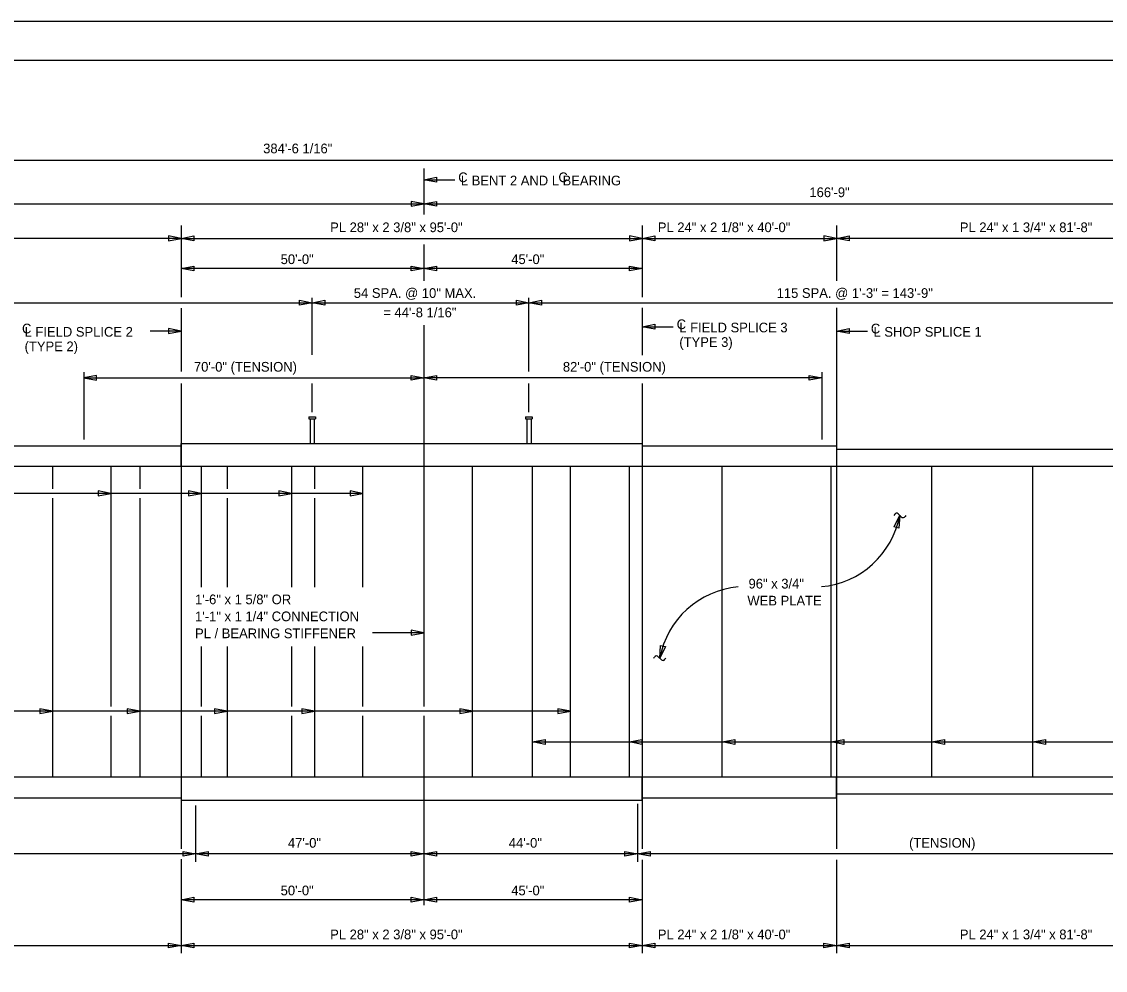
# Model space of a CAD drawing. Extents: x -305 to -161, y -187 to -99.
# Drawn here: x -249.7 to -193.9, y -148.4 to -99.5 of the extents above; entities that cross this region are included whole.
import ezdxf

# ---------------------------------------------------------------- set-up
doc = ezdxf.new("R2010")
doc.units = 0
for name, color, linetype in [('BR_AUTO DIMENSION', 7, 'Continuous'), ('BR_BORDER LINES', 7, 'Continuous'), ('BR_CENTER LINES', 7, 'Continuous'), ('BR_STRUCTURAL STEEL', 7, 'Continuous'), ('BR_TEXT', 7, 'Continuous'), ('Default', 7, 'Continuous'), ('Level 31', 7, 'Continuous')]:
    doc.layers.add(name, color=color, linetype=linetype)

msp = doc.modelspace()

# ---------------------------------------------------------------- linework, layer by layer
at = {"layer": 'BR_AUTO DIMENSION'}
for p, q in [((-284.433, -106.618), (-186.619, -106.618)), ((-228.973, -107.634), (-227.375, -107.634)), ((-284.433, -108.876), (-228.974, -108.876)), ((-228.974, -108.876), (-186.619, -108.876)), ((-241.473, -110.653), (-268.973, -110.653)), ((-241.473, -110.653), (-217.723, -110.653)), ((-217.723, -110.653), (-207.723, -110.653)), ((-186.619, -110.653), (-207.723, -110.653)), ((-228.973, -112.204), (-241.473, -112.204)), ((-217.723, -112.204), (-228.973, -112.204)), ((-234.724, -116.66), (-234.724, -113.721)), ((-223.557, -117.52), (-223.557, -113.721)), ((-282.099, -113.971), (-232.058, -113.971)), ((-282.099, -113.971), (-234.724, -113.971)), ((-234.724, -113.971), (-223.557, -113.971)), ((-223.557, -113.971), (-187.869, -113.971)), ((-241.473, -115.428), (-243.072, -115.428)), ((-217.723, -115.207), (-216.125, -115.207)), ((-207.723, -115.428), (-206.125, -115.428)), ((-246.473, -117.55), (-246.473, -121.025)), ((-208.473, -117.55), (-208.473, -121.025)), ((-246.473, -117.84), (-228.973, -117.84)), ((-234.724, -119.6), (-234.724, -118.13)), ((-208.473, -117.84), (-228.973, -117.84)), ((-223.557, -119.6), (-223.557, -118.13)), ((-232.123, -123.792), (-287.791, -123.792)), ((-228.973, -130.97), (-231.622, -130.97)), ((-221.422, -135.013), (-287.791, -135.013)), ((-223.369, -136.601), (-183.069, -136.601)), ((-240.723, -139.874), (-240.723, -142.773)), ((-217.973, -139.78), (-217.973, -142.773)), ((-240.723, -142.367), (-284.433, -142.367)), ((-228.973, -142.367), (-240.723, -142.367)), ((-217.973, -142.367), (-228.973, -142.367)), ((-186.619, -142.367), (-217.973, -142.367)), ((-228.973, -144.726), (-241.473, -144.726)), ((-217.723, -144.726), (-228.973, -144.726)), ((-268.973, -147.085), (-241.473, -147.085)), ((-241.473, -147.085), (-217.723, -147.085)), ((-217.723, -147.085), (-207.723, -147.085)), ((-207.723, -147.085), (-186.619, -147.085))]:
    msp.add_line(p, q, dxfattribs=at)
for points in [[(-228.323, -107.759), (-228.973, -107.634), (-228.323, -107.509)], [(-229.623, -109.001), (-228.973, -108.876), (-229.623, -108.751)], [(-228.323, -109.001), (-228.973, -108.876), (-228.323, -108.751)], [(-242.123, -110.778), (-241.473, -110.653), (-242.123, -110.528)], [(-240.823, -110.778), (-241.473, -110.653), (-240.823, -110.528)], [(-218.373, -110.778), (-217.723, -110.653), (-218.373, -110.528)], [(-217.073, -110.778), (-217.723, -110.653), (-217.073, -110.528)], [(-208.373, -110.778), (-207.723, -110.653), (-208.373, -110.528)], [(-207.073, -110.778), (-207.723, -110.653), (-207.073, -110.528)], [(-240.823, -112.329), (-241.473, -112.204), (-240.823, -112.079)], [(-229.623, -112.079), (-228.973, -112.204), (-229.623, -112.329)], [(-228.323, -112.329), (-228.973, -112.204), (-228.323, -112.079)], [(-218.373, -112.079), (-217.723, -112.204), (-218.373, -112.329)], [(-235.374, -113.846), (-234.724, -113.971), (-235.374, -114.096)], [(-234.074, -114.096), (-234.724, -113.971), (-234.074, -113.846)], [(-224.207, -113.846), (-223.557, -113.971), (-224.207, -114.096)], [(-222.907, -114.096), (-223.557, -113.971), (-222.907, -113.846)], [(-242.123, -115.553), (-241.473, -115.428), (-242.123, -115.303)], [(-217.073, -115.332), (-217.723, -115.207), (-217.073, -115.082)], [(-207.073, -115.553), (-207.723, -115.428), (-207.073, -115.303)], [(-245.823, -117.715), (-246.473, -117.84), (-245.823, -117.965)], [(-229.623, -117.715), (-228.973, -117.84), (-229.623, -117.965)], [(-228.323, -117.965), (-228.973, -117.84), (-228.323, -117.715)], [(-209.123, -117.715), (-208.473, -117.84), (-209.123, -117.965)], [(-245.735, -123.917), (-245.085, -123.792), (-245.735, -123.667)], [(-241.089, -123.917), (-240.439, -123.792), (-241.089, -123.667)], [(-236.442, -123.917), (-235.792, -123.792), (-236.442, -123.667)], [(-232.773, -123.917), (-232.123, -123.792), (-232.773, -123.667)], [(-204.748, -125.52), (-204.465, -124.922), (-204.506, -125.582)], [(-229.623, -131.095), (-228.973, -130.97), (-229.623, -130.845)], [(-216.534, -131.689), (-216.817, -132.287), (-216.776, -131.627)], [(-248.749, -135.138), (-248.099, -135.013), (-248.749, -134.888)], [(-244.249, -135.138), (-243.599, -135.013), (-244.249, -134.888)], [(-239.749, -135.138), (-239.099, -135.013), (-239.749, -134.888)], [(-235.249, -135.138), (-234.599, -135.013), (-235.249, -134.888)], [(-227.123, -135.138), (-226.473, -135.013), (-227.123, -134.888)], [(-222.072, -135.138), (-221.422, -135.013), (-222.072, -134.888)], [(-222.719, -136.726), (-223.369, -136.601), (-222.719, -136.476)], [(-217.739, -136.726), (-218.389, -136.601), (-217.739, -136.476)], [(-212.952, -136.726), (-213.602, -136.601), (-212.952, -136.476)], [(-207.351, -136.726), (-208.001, -136.601), (-207.351, -136.476)], [(-202.156, -136.726), (-202.806, -136.601), (-202.156, -136.476)], [(-196.962, -136.726), (-197.612, -136.601), (-196.962, -136.476)], [(-241.373, -142.242), (-240.723, -142.367), (-241.373, -142.492)], [(-240.073, -142.492), (-240.723, -142.367), (-240.073, -142.242)], [(-229.623, -142.242), (-228.973, -142.367), (-229.623, -142.492)], [(-228.323, -142.492), (-228.973, -142.367), (-228.323, -142.242)], [(-218.623, -142.242), (-217.973, -142.367), (-218.623, -142.492)], [(-217.323, -142.492), (-217.973, -142.367), (-217.323, -142.242)], [(-240.823, -144.851), (-241.473, -144.726), (-240.823, -144.601)], [(-229.623, -144.601), (-228.973, -144.726), (-229.623, -144.851)], [(-228.323, -144.851), (-228.973, -144.726), (-228.323, -144.601)], [(-218.373, -144.601), (-217.723, -144.726), (-218.373, -144.851)], [(-242.123, -146.96), (-241.473, -147.085), (-242.123, -147.21)], [(-240.823, -147.21), (-241.473, -147.085), (-240.823, -146.96)], [(-218.373, -146.96), (-217.723, -147.085), (-218.373, -147.21)], [(-217.073, -147.21), (-217.723, -147.085), (-217.073, -146.96)], [(-208.373, -146.96), (-207.723, -147.085), (-208.373, -147.21)], [(-207.073, -147.21), (-207.723, -147.085), (-207.073, -146.96)]]:
    msp.add_lwpolyline(points, close=True, dxfattribs=at)
for centre, start, end in [((-208.89, -124.118), 274.9624, 349.7037), ((-212.392, -133.091), 94.9624, 169.7037)]:
    msp.add_arc(centre, 4.497, start, end, dxfattribs=at)
at = {"layer": 'BR_BORDER LINES'}
msp.add_line((-163.178, -101.489), (-297.843, -101.489), dxfattribs=at)
at = {"layer": 'BR_CENTER LINES'}
for p, q in [((-228.973, -107.059), (-228.973, -109.43)), ((-241.473, -109.997), (-241.473, -113.69)), ((-217.723, -109.997), (-217.723, -113.69)), ((-207.723, -109.997), (-207.723, -112.835)), ((-228.973, -110.967), (-228.973, -112.835)), ((-241.473, -114.253), (-241.473, -117.52)), ((-217.723, -114.23), (-217.723, -116.675)), ((-207.723, -114.23), (-207.723, -142.108)), ((-228.973, -115.133), (-228.973, -122.412)), ((-241.473, -118.13), (-241.473, -124.614)), ((-217.723, -118.13), (-217.723, -142.11)), ((-241.473, -124.614), (-241.473, -142.109)), ((-228.973, -138.412), (-228.973, -145.014)), ((-241.473, -142.631), (-241.473, -147.486)), ((-217.723, -142.664), (-217.723, -147.486)), ((-207.723, -142.667), (-207.723, -147.486))]:
    msp.add_line(p, q, dxfattribs=at)
at = {"layer": 'BR_STRUCTURAL STEEL'}
for p, q in [((-268.973, -121.35), (-241.473, -121.35)), ((-241.473, -122.412), (-241.473, -121.225)), ((-241.473, -121.225), (-217.723, -121.225)), ((-217.723, -121.225), (-217.723, -122.412)), ((-217.723, -121.35), (-207.723, -121.35)), ((-207.723, -121.35), (-207.723, -122.412)), ((-186.619, -121.537), (-207.723, -121.537)), ((-186.619, -122.412), (-284.433, -122.412)), ((-248.099, -122.412), (-248.099, -123.55)), ((-245.085, -122.412), (-245.085, -134.771)), ((-243.599, -122.412), (-243.599, -123.55)), ((-240.439, -122.412), (-240.439, -128.632)), ((-239.099, -122.412), (-239.099, -123.55)), ((-235.792, -122.412), (-235.792, -128.632)), ((-234.599, -122.412), (-234.599, -123.55)), ((-232.123, -122.412), (-232.123, -128.632)), ((-228.973, -122.412), (-228.973, -134.771)), ((-226.473, -138.412), (-226.473, -122.412)), ((-223.369, -138.412), (-223.369, -122.412)), ((-221.422, -138.412), (-221.422, -122.412)), ((-218.389, -138.412), (-218.389, -122.412)), ((-213.602, -138.412), (-213.602, -122.412)), ((-208.001, -138.412), (-208.001, -122.412)), ((-202.806, -138.412), (-202.806, -122.412)), ((-197.612, -138.412), (-197.612, -122.412)), ((-248.099, -124.034), (-248.099, -138.412)), ((-243.599, -124.034), (-243.599, -138.412)), ((-239.099, -124.034), (-239.099, -128.632)), ((-234.599, -124.034), (-234.599, -128.632)), ((-240.439, -131.688), (-240.439, -134.771)), ((-239.099, -131.688), (-239.099, -138.412)), ((-235.792, -131.688), (-235.792, -134.771)), ((-234.599, -131.688), (-234.599, -138.412)), ((-232.123, -131.688), (-232.123, -134.771)), ((-245.085, -135.255), (-245.085, -138.412)), ((-240.439, -135.255), (-240.439, -138.412)), ((-235.792, -135.255), (-235.792, -138.412)), ((-232.123, -135.255), (-232.123, -138.412)), ((-228.973, -135.255), (-228.973, -138.412)), ((-186.619, -138.412), (-284.433, -138.412)), ((-241.473, -138.412), (-241.473, -139.6)), ((-217.723, -139.6), (-217.723, -138.412)), ((-207.723, -139.475), (-207.723, -138.412)), ((-268.973, -139.475), (-241.473, -139.475)), ((-217.724, -139.475), (-207.723, -139.475)), ((-186.619, -139.287), (-207.723, -139.287)), ((-241.473, -139.6), (-217.724, -139.6))]:
    msp.add_line(p, q, dxfattribs=at)
at = {"layer": 'BR_TEXT'}
for p, q in [((-204.725, -124.869), (-204.768, -124.93)), ((-204.384, -124.996), (-204.547, -124.847)), ((-204.15, -124.93), (-204.18, -124.976)), ((-217.131, -132.279), (-217.102, -132.233)), ((-216.898, -132.213), (-216.735, -132.362)), ((-216.557, -132.34), (-216.514, -132.279))]:
    msp.add_line(p, q, dxfattribs=at)
for centre, radius, start, end in [((-204.627, -124.922), 0.111, 43.4519, 151.7375), ((-204.29, -124.915), 0.125, 221.007, 330.8059), ((-216.992, -132.294), 0.125, 41.007, 150.8059), ((-216.654, -132.287), 0.111, 223.4519, 331.7375)]:
    msp.add_arc(centre, radius, start, end, dxfattribs=at)
at = {"layer": 'Default'}
for p, q in [((-234.896, -119.85), (-234.896, -119.944)), ((-234.896, -119.85), (-234.552, -119.85)), ((-234.896, -119.944), (-234.552, -119.944)), ((-234.834, -119.944), (-234.834, -121.225)), ((-234.615, -119.944), (-234.615, -121.225)), ((-234.552, -119.85), (-234.552, -119.944)), ((-223.729, -119.85), (-223.729, -119.944)), ((-223.729, -119.85), (-223.385, -119.85)), ((-223.729, -119.944), (-223.385, -119.944)), ((-223.666, -119.944), (-223.666, -121.225)), ((-223.447, -119.944), (-223.447, -121.225)), ((-223.385, -119.85), (-223.385, -119.944))]:
    msp.add_line(p, q, dxfattribs=at)
at = {"layer": 'Level 31'}
msp.add_lwpolyline([(-305.176, -187.489), (-161.176, -187.489), (-161.176, -99.489), (-305.176, -99.489)], close=True, dxfattribs=at)

# ---------------------------------------------------------------- texts
at = {"layer": 'BR_AUTO DIMENSION'}
for s, p in [('384\'-6 1/16"', (-237.246, -106.272)), ('166\'-9"', (-209.116, -108.53)), ('PL 28" x 2 3/8" x 95\'-0"', (-233.797, -110.334)), ('PL 24" x 2 1/8" x 40\'-0"', (-216.922, -110.334)), ('PL 24" x 1 3/4" x 81\'-8"', (-201.37, -110.334)), ('50\'-0"', (-236.345, -111.979)), ('45\'-0"', (-224.47, -111.979)), (' 82\'-0" (TENSION)', (-221.997, -117.521)), ('96" x 3/4" ', (-212.251, -128.694)), ('WEB PLATE', (-212.309, -129.569)), ('47\'-0"', (-235.97, -142.048)), ('(TENSION)', (-203.983, -142.048)), ('50\'-0"', (-236.345, -144.501)), ('45\'-0"', (-224.47, -144.501)), ('PL 28" x 2 3/8" x 95\'-0"', (-233.797, -146.766)), ('PL 24" x 2 1/8" x 40\'-0"', (-216.922, -146.766)), ('PL 24" x 1 3/4" x 81\'-8"', (-201.37, -146.766))]:
    msp.add_text(s, height=0.5, rotation=360, dxfattribs=at).set_placement(p)
for s, p in [('54 SPA. @ 10" MAX.', (-232.578, -113.721)), ('115 SPA. @ 1\'-3" = 143\'-9"', (-210.803, -113.721)), ('= 44\'-8 1/16"', (-231.059, -114.721)), (' 70\'-0" (TENSION)', (-240.997, -117.521)), ('44\'-0"', (-224.595, -142.048))]:
    msp.add_text(s, height=0.5, dxfattribs=at).set_placement(p)
at = {"layer": 'BR_TEXT'}
for s, p in [('C', (-227.201, -107.758)), ('L BENT 2 AND L BEARING', (-227.065, -107.924)), ('C', (-222.041, -107.758)), ('C', (-215.951, -115.33)), ('C', (-249.666, -115.551)), ('L FIELD SPLICE 2', (-249.531, -115.718)), ('L FIELD SPLICE 3', (-215.815, -115.497)), ('C', (-205.951, -115.551)), ('L SHOP SPLICE 1', (-205.815, -115.718)), ('(TYPE 2)', (-249.531, -116.468)), ('(TYPE 3)', (-215.815, -116.247)), ('1\'-6" x 1 5/8" OR', (-240.753, -129.504)), ('1\'-1" x 1 1/4" CONNECTION ', (-240.753, -130.379)), ('PL / BEARING STIFFENER', (-240.753, -131.254))]:
    msp.add_text(s, height=0.5, rotation=360, dxfattribs=at).set_placement(p)

doc.saveas('drawing.dxf')
